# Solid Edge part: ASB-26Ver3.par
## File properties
Author: nakano
Template: iso metric part.par
Last saved by: nakano
Revision: 2
Application: Solid Edge
Accuracy: 0.990
Username: nakano
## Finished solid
Body 1: solid body, 40 faces, 84 edges, 32 vertices.
  Faces by surface: cylinder 20, plane 20
  Edges by curve: line 44, circle 40
Bounding box of the edges (mm): 52.248 x 63.106 x 24.613, from (-26.1239, -1.524, -12.3063) to (26.1239, 61.5823, 12.3063).
Cylindrical faces by radius (mm): R0.8128 x2, R1.1938 x8, R1.5875 x4, R2.3368 x2, R4.0005 x2, R12.3063 x2
Planar faces by outward normal: +x 3, +y 1, +z 6, -x 3, -y 1, -z 6
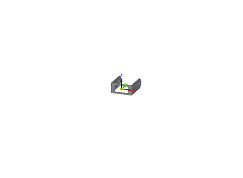
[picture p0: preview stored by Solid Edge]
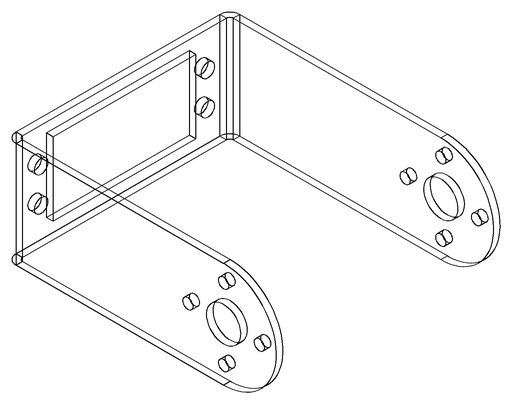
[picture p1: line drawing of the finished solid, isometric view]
